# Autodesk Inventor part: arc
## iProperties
Shininess: 64.0
Length Units: 11269
Angle Units: 11279
Time Units: 11290
Mass Units: 11286
Length Display Precision: 1
Angle Display Precision: 2
Compacted: True
Part Number: arc
Document SubType Name: Modeling
Created: 2002-11
Designer: Elise Moss
Density: 0.0
Volumn: 0.0
Area: 0.0
PropertySet Name: Model Information
Control State: 0
Master: False
Checked Out: False
Author: Elise Moss
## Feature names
1. Extrusion1
2. Split1
3. Hole1
4. Mirror1
